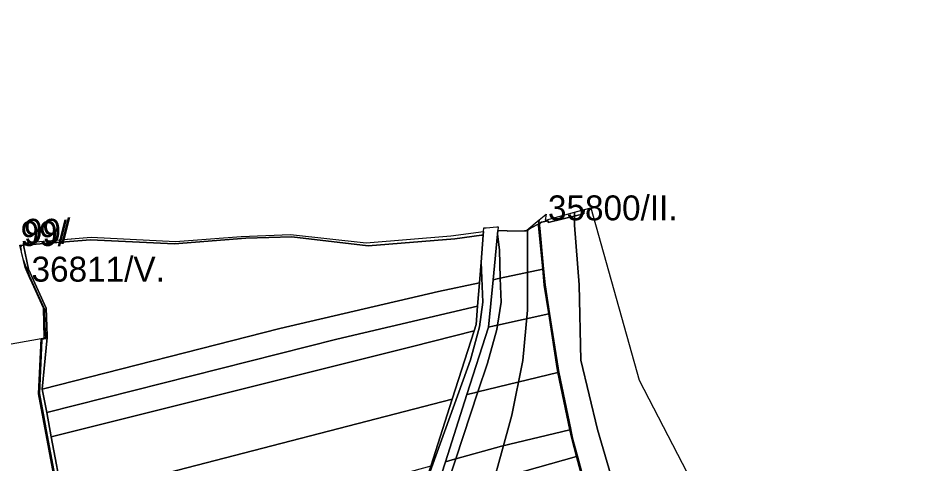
# Model space of a CAD drawing. Extents: x -535894 to -532827, y -1165802 to -1163635.
# Drawn here: x -534170 to -533625, y -1164021 to -1163752 of the extents above; entities that cross this region are included whole.
import ezdxf

# ---------------------------------------------------------------- set-up
doc = ezdxf.new("R2010")
doc.units = 0
for name, color, linetype in [('BPEJ_s', 7, 'Continuous'), ('orna_s', 7, 'Continuous'), ('ostatni_s', 7, 'Continuous'), ('PUPFL_s', 7, 'Continuous'), ('voda_s', 7, 'Continuous')]:
    doc.layers.add(name, color=color, linetype=linetype)

msp = doc.modelspace()

# ---------------------------------------------------------------- linework, layer by layer
at = {"layer": 'BPEJ_s'}
for points in [[(-533856.167, -1163875.563), (-533862.278, -1163879.083), (-533862.503, -1163879.213), (-533863.428, -1163879.746), (-533864.249, -1163880.219), (-533864.98, -1163880.231), (-533875.795, -1163880.402), (-533875.769, -1163880.123), (-533866.68, -1163880.24), (-533863.98, -1163879.91), (-533856.45, -1163873.6), (-533853.53, -1163871.16), (-533852.38, -1163870.19), (-533852.91, -1163873.85), (-533850.38, -1163873.16), (-533835.15, -1163868.99), (-533829.496, -1163867.438), (-533829.601, -1163869.964), (-533834.627, -1163871.207), (-533851.075, -1163875.277), (-533851.075, -1163874.179), (-533855.193, -1163875.002)], [(-534166.675, -1163888.675), (-534166.956, -1163888.683), (-534167.05, -1163887.54), (-534164.382, -1163887.317), (-534163.89, -1163887.698), (-534166.45, -1163887.899), (-534166.395, -1163888.611), (-534166.649, -1163888.63)], [(-534168.86, -1163889.84), (-534168.438, -1163892.06), (-534169.16, -1163888.95), (-534168.411, -1163888.926), (-534168.548, -1163889.001), (-534168.37, -1163889.768)], [(-534161.827, -1163911.667), (-534162.72, -1163909.691), (-534162, -1163911.1)]]:
    msp.add_lwpolyline(points, close=True, dxfattribs=at)
for points in [[(-533856.167, -1163878.726), (-533856.34, -1163876.946), (-533856.305, -1163876.665), (-533856.167, -1163875.563), (-533855.193, -1163875.002), (-533851.075, -1163874.179), (-533851.075, -1163875.277), (-533834.627, -1163871.207), (-533829.601, -1163869.964), (-533829.496, -1163867.438), (-533825.35, -1163866.3)], [(-533825.35, -1163866.3), (-533796.36, -1163970.1), (-533744.41, -1164070.17), (-533714.01, -1164096.6), (-533693.46, -1164114.46), (-533686.62, -1164120.4), (-533678.92, -1164127.1), (-533637.25, -1164163.31), (-533513.14, -1164200.59)], [(-533914.47, -1164142.17), (-533875.366, -1164000), (-533872.97, -1163991.29), (-533866.29, -1163958.32), (-533863.428, -1163928.06), (-533863.428, -1163879.746), (-533862.503, -1163879.213), (-533862.278, -1163879.083), (-533856.167, -1163875.563), (-533856.305, -1163876.665), (-533856.34, -1163876.946), (-533856.167, -1163878.726), (-533853.814, -1163903.093), (-533852.874, -1163912.824), (-533850.209, -1163930.114), (-533845.148, -1163962.951), (-533844.65, -1163965.351), (-533837.451, -1163999.854), (-533837.421, -1164000), (-533836.361, -1164005.076), (-533833.428, -1164015.976), (-533828.813, -1164033.1)], [(-534145.49, -1164041.708), (-534153.303, -1164000), (-534154.963, -1163991.136), (-534157.384, -1163978.211), (-534155.912, -1163946.108), (-534155.882, -1163945.429), (-534153.502, -1163945.012), (-534154.189, -1163937.323), (-534154.386, -1163927.396), (-534163.349, -1163907.55), (-534165.3, -1163902.526), (-534165.559, -1163901.864), (-534167.061, -1163897.999), (-534168.438, -1163892.06), (-534168.86, -1163889.84), (-534168.37, -1163889.768), (-534168.548, -1163889.001), (-534168.411, -1163888.926), (-534166.94, -1163888.88), (-534166.956, -1163888.683), (-534166.675, -1163888.675), (-534166.649, -1163888.63), (-534166.395, -1163888.611), (-534166.45, -1163887.899), (-534163.89, -1163887.698), (-534164.382, -1163887.317), (-534126.29, -1163884.14), (-534075.55, -1163886.63), (-534035.93, -1163883.59), (-534006.23, -1163882.44), (-533960.63, -1163887.47), (-533909.61, -1163883.3), (-533889.94, -1163880.68), (-533889.77, -1163878.53), (-533888.35, -1163878.41), (-533881.96, -1163877.92), (-533881.19, -1163877.86), (-533881.4, -1163880.05), (-533875.769, -1163880.123), (-533875.795, -1163880.402), (-533864.98, -1163880.231), (-533864.249, -1163880.219), (-533863.428, -1163879.746), (-533863.428, -1163928.06), (-533866.29, -1163958.32), (-533872.97, -1163991.29), (-533875.366, -1164000), (-533914.47, -1164142.17)], [(-533828.813, -1164033.1), (-533833.428, -1164015.976), (-533836.361, -1164005.076), (-533837.421, -1164000), (-533837.451, -1163999.854), (-533844.65, -1163965.351), (-533845.148, -1163962.951), (-533850.209, -1163930.114), (-533852.874, -1163912.824), (-533853.814, -1163903.093), (-533856.167, -1163878.726)], [(-534224.22, -1163957.18), (-534156.41, -1163945.04), (-534154.6, -1163944.72), (-534154.95, -1163926.9), (-534161.827, -1163911.667), (-534162, -1163911.1), (-534162.72, -1163909.691), (-534166.07, -1163902.27), (-534167.061, -1163897.999), (-534165.559, -1163901.864), (-534165.3, -1163902.526), (-534163.349, -1163907.55), (-534154.386, -1163927.396), (-534154.189, -1163937.323), (-534153.502, -1163945.012), (-534155.882, -1163945.429), (-534155.912, -1163946.108), (-534157.384, -1163978.211), (-534154.963, -1163991.136), (-534153.303, -1164000), (-534145.49, -1164041.708)]]:
    msp.add_lwpolyline(points, dxfattribs=at)
at = {"layer": 'orna_s'}
for points in [[(-533856.89, -1163877.14), (-533854.37, -1163903.29), (-533879.91, -1163908.81), (-533880.47, -1163891.74), (-533881.62, -1163882.25), (-533881.4, -1163880.05), (-533866.68, -1163880.24), (-533863.98, -1163879.91), (-533856.45, -1163873.6)], [(-533890.12, -1163882.84), (-533891.13, -1163882.88), (-533907.32, -1163885.02), (-533959.54, -1163889.18), (-534005.5, -1163883.9), (-534033.11, -1163884.59), (-534076.08, -1163888.15), (-534126.63, -1163885.69), (-534166.94, -1163888.88), (-534167.05, -1163887.54), (-534126.29, -1163884.14), (-534075.55, -1163886.63), (-534035.93, -1163883.59), (-534006.23, -1163882.44), (-533960.63, -1163887.47), (-533909.61, -1163883.3), (-533889.94, -1163880.68)], [(-533890.12, -1163882.84), (-533891.45, -1163899.11), (-533892.46, -1163911.51), (-533917.11, -1163916.82), (-534012.6, -1163939), (-534155.71, -1163975.68), (-534152.8, -1163944.4), (-534152.71, -1163943.44), (-534153.31, -1163926.88), (-534163.98, -1163903.4), (-534166.94, -1163888.88), (-534126.63, -1163885.69), (-534076.08, -1163888.15), (-534033.11, -1163884.59), (-534005.5, -1163883.9), (-533959.54, -1163889.18), (-533907.32, -1163885.02), (-533891.13, -1163882.88)], [(-533879.91, -1163908.81), (-533854.37, -1163903.29), (-533853.43, -1163913.02), (-533850.77, -1163930.31), (-533881.54, -1163937.07), (-533879.45, -1163923.12)], [(-533917.11, -1163916.82), (-533892.46, -1163911.51), (-533893.61, -1163925.64), (-533978.28, -1163945.56), (-534153.06, -1163989.73), (-534155.71, -1163975.68), (-534012.6, -1163939)], [(-533894.49, -1163936.59), (-533895.7, -1163940.37), (-533932.68, -1163949.92), (-534150.32, -1164004.31), (-534153.06, -1163989.73), (-533978.28, -1163945.56), (-533893.61, -1163925.64)], [(-533881.54, -1163937.07), (-533850.77, -1163930.31), (-533845.71, -1163963.15), (-533845.21, -1163965.55), (-533893.35, -1163977.24), (-533887.65, -1163959.99), (-533881.92, -1163939.56)], [(-533895.7, -1163940.37), (-533908.87, -1163981.51), (-534085.67, -1164027.32), (-534143.34, -1164041.3), (-534150.32, -1164004.31), (-533932.68, -1163949.92)], [(-533893.35, -1163977.24), (-533845.21, -1163965.55), (-533838.01, -1164000.05), (-533879.17, -1164009.99), (-533906.69, -1164017.55)], [(-533921.81, -1164021.92), (-533995.77, -1164042.33), (-534077.52, -1164062.7), (-534136.93, -1164080.66), (-534142.42, -1164063.29), (-534143.34, -1164041.3), (-534085.67, -1164027.32), (-533908.87, -1163981.51)], [(-533836.92, -1164005.27), (-533833.99, -1164016.17), (-533913.66, -1164038.64), (-533906.69, -1164017.55), (-533879.17, -1164009.99), (-533838.01, -1164000.05)], [(-533829.37, -1164033.3), (-533920.66, -1164059.82), (-533916.23, -1164046.38), (-533913.66, -1164038.64), (-533833.99, -1164016.17)]]:
    msp.add_lwpolyline(points, close=True, dxfattribs=at)
at = {"layer": 'ostatni_s'}
for points in [[(-533853.53, -1163871.16), (-533852.38, -1163870.19), (-533852.91, -1163873.85), (-533850.38, -1163873.16), (-533835.15, -1163868.99), (-533835.25, -1163876.86), (-533832.51, -1163912.75), (-533831.47, -1163958.19), (-533821.43, -1163999.88), (-533807.37, -1164047.78), (-533785.98, -1164100.6), (-533771.58, -1164135.97), (-533760.11, -1164157.23), (-533736.29, -1164196.18), (-533708.99, -1164234.05), (-533688.28, -1164260.76), (-533659.7, -1164292.03), (-533637.12, -1164313.74), (-533614.65, -1164333.34), (-533574.57, -1164364.55), (-533529.97, -1164399.56), (-533437.52, -1164471.63), (-533404.17, -1164500.26), (-533365.03, -1164536.67)], [(-533829.37, -1164033.3), (-533833.99, -1164016.17), (-533836.92, -1164005.27), (-533838.01, -1164000.05), (-533845.21, -1163965.55), (-533845.71, -1163963.15), (-533850.77, -1163930.31), (-533853.43, -1163913.02), (-533854.37, -1163903.29), (-533856.89, -1163877.14), (-533856.45, -1163873.6), (-533853.53, -1163871.16)], [(-533928.41, -1164042.51), (-533897.78, -1163957.92), (-533892.48, -1163938), (-533890.48, -1163923.29), (-533891.45, -1163899.11), (-533890.12, -1163882.84), (-533889.94, -1163880.68), (-533889.77, -1163878.53), (-533888.35, -1163878.41), (-533881.96, -1163877.92), (-533881.19, -1163877.86), (-533881.4, -1163880.05), (-533881.62, -1163882.25), (-533884.29, -1163909.75), (-533887.08, -1163938.28), (-533900.03, -1163978.86), (-533912.94, -1164019.27), (-533919.67, -1164040.34)], [(-534146.05, -1164041.92), (-534157.94, -1163978.43), (-534156.41, -1163945.04), (-534154.6, -1163944.72), (-534152.8, -1163944.4), (-534155.71, -1163975.68), (-534153.06, -1163989.73), (-534150.32, -1164004.31), (-534143.34, -1164041.3)]]:
    msp.add_lwpolyline(points, dxfattribs=at)
for points in [[(-533881.62, -1163882.25), (-533880.47, -1163891.74), (-533879.91, -1163908.81), (-533881.75, -1163909.2), (-533884.29, -1163909.75)], [(-534169.16, -1163888.95), (-534166.94, -1163888.88), (-534163.98, -1163903.4), (-534153.31, -1163926.88), (-534152.71, -1163943.44), (-534152.8, -1163944.4), (-534154.6, -1163944.72), (-534154.95, -1163926.9), (-534166.07, -1163902.27)], [(-533892.46, -1163911.51), (-533891.45, -1163899.11), (-533890.48, -1163923.29), (-533892.48, -1163938), (-533897.78, -1163957.92), (-533928.41, -1164042.51), (-533921.81, -1164021.92), (-533908.87, -1163981.51), (-533895.7, -1163940.37), (-533894.49, -1163936.59), (-533893.61, -1163925.64)], [(-533881.75, -1163909.2), (-533879.91, -1163908.81), (-533879.45, -1163923.12), (-533881.54, -1163937.07), (-533883.64, -1163937.53), (-533887.08, -1163938.28), (-533884.29, -1163909.75)], [(-533883.64, -1163937.53), (-533881.54, -1163937.07), (-533881.92, -1163939.56), (-533887.65, -1163959.99), (-533893.35, -1163977.24), (-533895.38, -1163977.72), (-533900.03, -1163978.86), (-533887.08, -1163938.28)], [(-533895.38, -1163977.72), (-533893.35, -1163977.24), (-533906.69, -1164017.55), (-533908.91, -1164018.16), (-533912.94, -1164019.27), (-533900.03, -1163978.86)], [(-533908.91, -1164018.16), (-533906.69, -1164017.55), (-533913.66, -1164038.64), (-533915.99, -1164039.3), (-533919.67, -1164040.34), (-533912.94, -1164019.27)]]:
    msp.add_lwpolyline(points, close=True, dxfattribs=at)
at = {"layer": 'PUPFL_s'}
msp.add_lwpolyline([(-534427.72, -1163752.13), (-534413.24, -1163763.36), (-534362.72, -1163807.37), (-534355.93, -1163819.24), (-534338.84, -1163838.27), (-534314.16, -1163855.97), (-534296.47, -1163870.97), (-534271.49, -1163905.38), (-534250.57, -1163903.14), (-534241.76, -1163894.34), (-534224.22, -1163957.18), (-534156.41, -1163945.04), (-534157.94, -1163978.43), (-534146.05, -1164041.92), (-534145.18, -1164064.32), (-534137.15, -1164087.2), (-534425.41, -1164026.54)], close=True, dxfattribs=at)
at = {"layer": 'voda_s'}
msp.add_lwpolyline([(-533614.65, -1164333.34), (-533637.12, -1164313.74), (-533659.7, -1164292.03), (-533688.28, -1164260.76), (-533708.99, -1164234.05), (-533736.29, -1164196.18), (-533760.11, -1164157.23), (-533771.58, -1164135.97), (-533785.98, -1164100.6), (-533807.37, -1164047.78), (-533821.43, -1163999.88), (-533831.47, -1163958.19), (-533832.51, -1163912.75), (-533835.25, -1163876.86), (-533835.15, -1163868.99), (-533825.35, -1163866.3), (-533796.36, -1163970.1), (-533744.41, -1164070.17), (-533714.01, -1164096.6), (-533675.79, -1164164.9), (-533652.75, -1164196.64), (-533615.89, -1164239.81)], dxfattribs=at)

# ---------------------------------------------------------------- texts
at = {"layer": 'BPEJ_s'}
for s, p in [('35800/II.', (-533851.211, -1163873.92)), ('99/', (-534168.765, -1163889.382)), ('99/', (-534166.727, -1163888)), ('36811/V.', (-534162.182, -1163910.819))]:
    msp.add_text(s, height=15, dxfattribs=at).set_placement(p)

doc.saveas('drawing.dxf')
